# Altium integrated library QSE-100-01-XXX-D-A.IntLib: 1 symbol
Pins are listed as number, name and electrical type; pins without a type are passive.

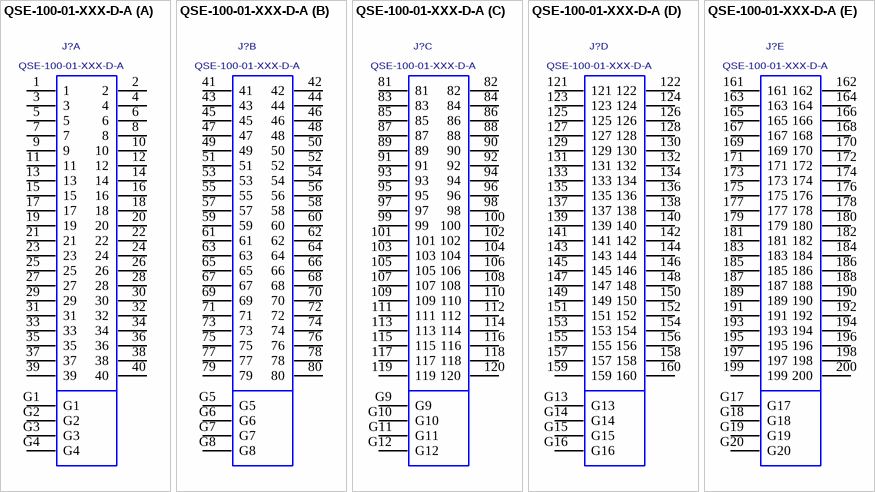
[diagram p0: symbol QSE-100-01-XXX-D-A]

## QSE-100-01-XXX-D-A
designator J?
HIGH SPEED SOCKET STRIP, .8mm PITCH, 200 PINS.; MANUFACTURER: SAMTEC
footprint QSE-100-01-XXX-D-A
part A pins: 1, 2, 3, 4, 5, 6, 7, 8, 9, 10, 11, 12, 13, 14, 15, 16, 17, 18, 19, 20, 21, 22, 23, 24, 25, 26, 27, 28, 29, 30, 31, 32, 33, 34, 35, 36, 37, 38, 39, 40, G1, G2, G3, G4
part B pins: 41, 42, 43, 44, 45, 46, 47, 48, 49, 50, 51, 52, 53, 54, 55, 56, 57, 58, 59, 60, 61, 62, 63, 64, 65, 66, 67, 68, 69, 70, 71, 72, 73, 74, 75, 76, 77, 78, 79, 80, G5, G6, G7, G8
part C pins: 81, 82, 83, 84, 85, 86, 87, 88, 89, 90, 91, 92, 93, 94, 95, 96, 97, 98, 99, 100, 101, 102, 103, 104, 105, 106, 107, 108, 109, 110, 111, 112, 113, 114, 115, 116, 117, 118, 119, 120, G9, G10, G11, G12
part D pins: 121, 122, 123, 124, 125, 126, 127, 128, 129, 130, 131, 132, 133, 134, 135, 136, 137, 138, 139, 140, 141, 142, 143, 144, 145, 146, 147, 148, 149, 150, 151, 152, 153, 154, 155, 156, 157, 158, 159, 160, G13, G14, G15, G16
part E pins: 161, 162, 163, 164, 165, 166, 167, 168, 169, 170, 171, 172, 173, 174, 175, 176, 177, 178, 179, 180, 181, 182, 183, 184, 185, 186, 187, 188, 189, 190, 191, 192, 193, 194, 195, 196, 197, 198, 199, 200, G17, G18, G19, G20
